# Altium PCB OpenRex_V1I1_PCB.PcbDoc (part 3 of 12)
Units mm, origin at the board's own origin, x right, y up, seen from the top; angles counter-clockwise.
Board outline 70 x 95 mm, 10 copper layers (L1, L2, L3, L4 (PWR), L5 (PWR), L6 (PWR), L7 (PWR), L8, L9, L10), stack 1.632 mm thick; 1080 components, 708 nets, 3831 pads, 2373 vias.
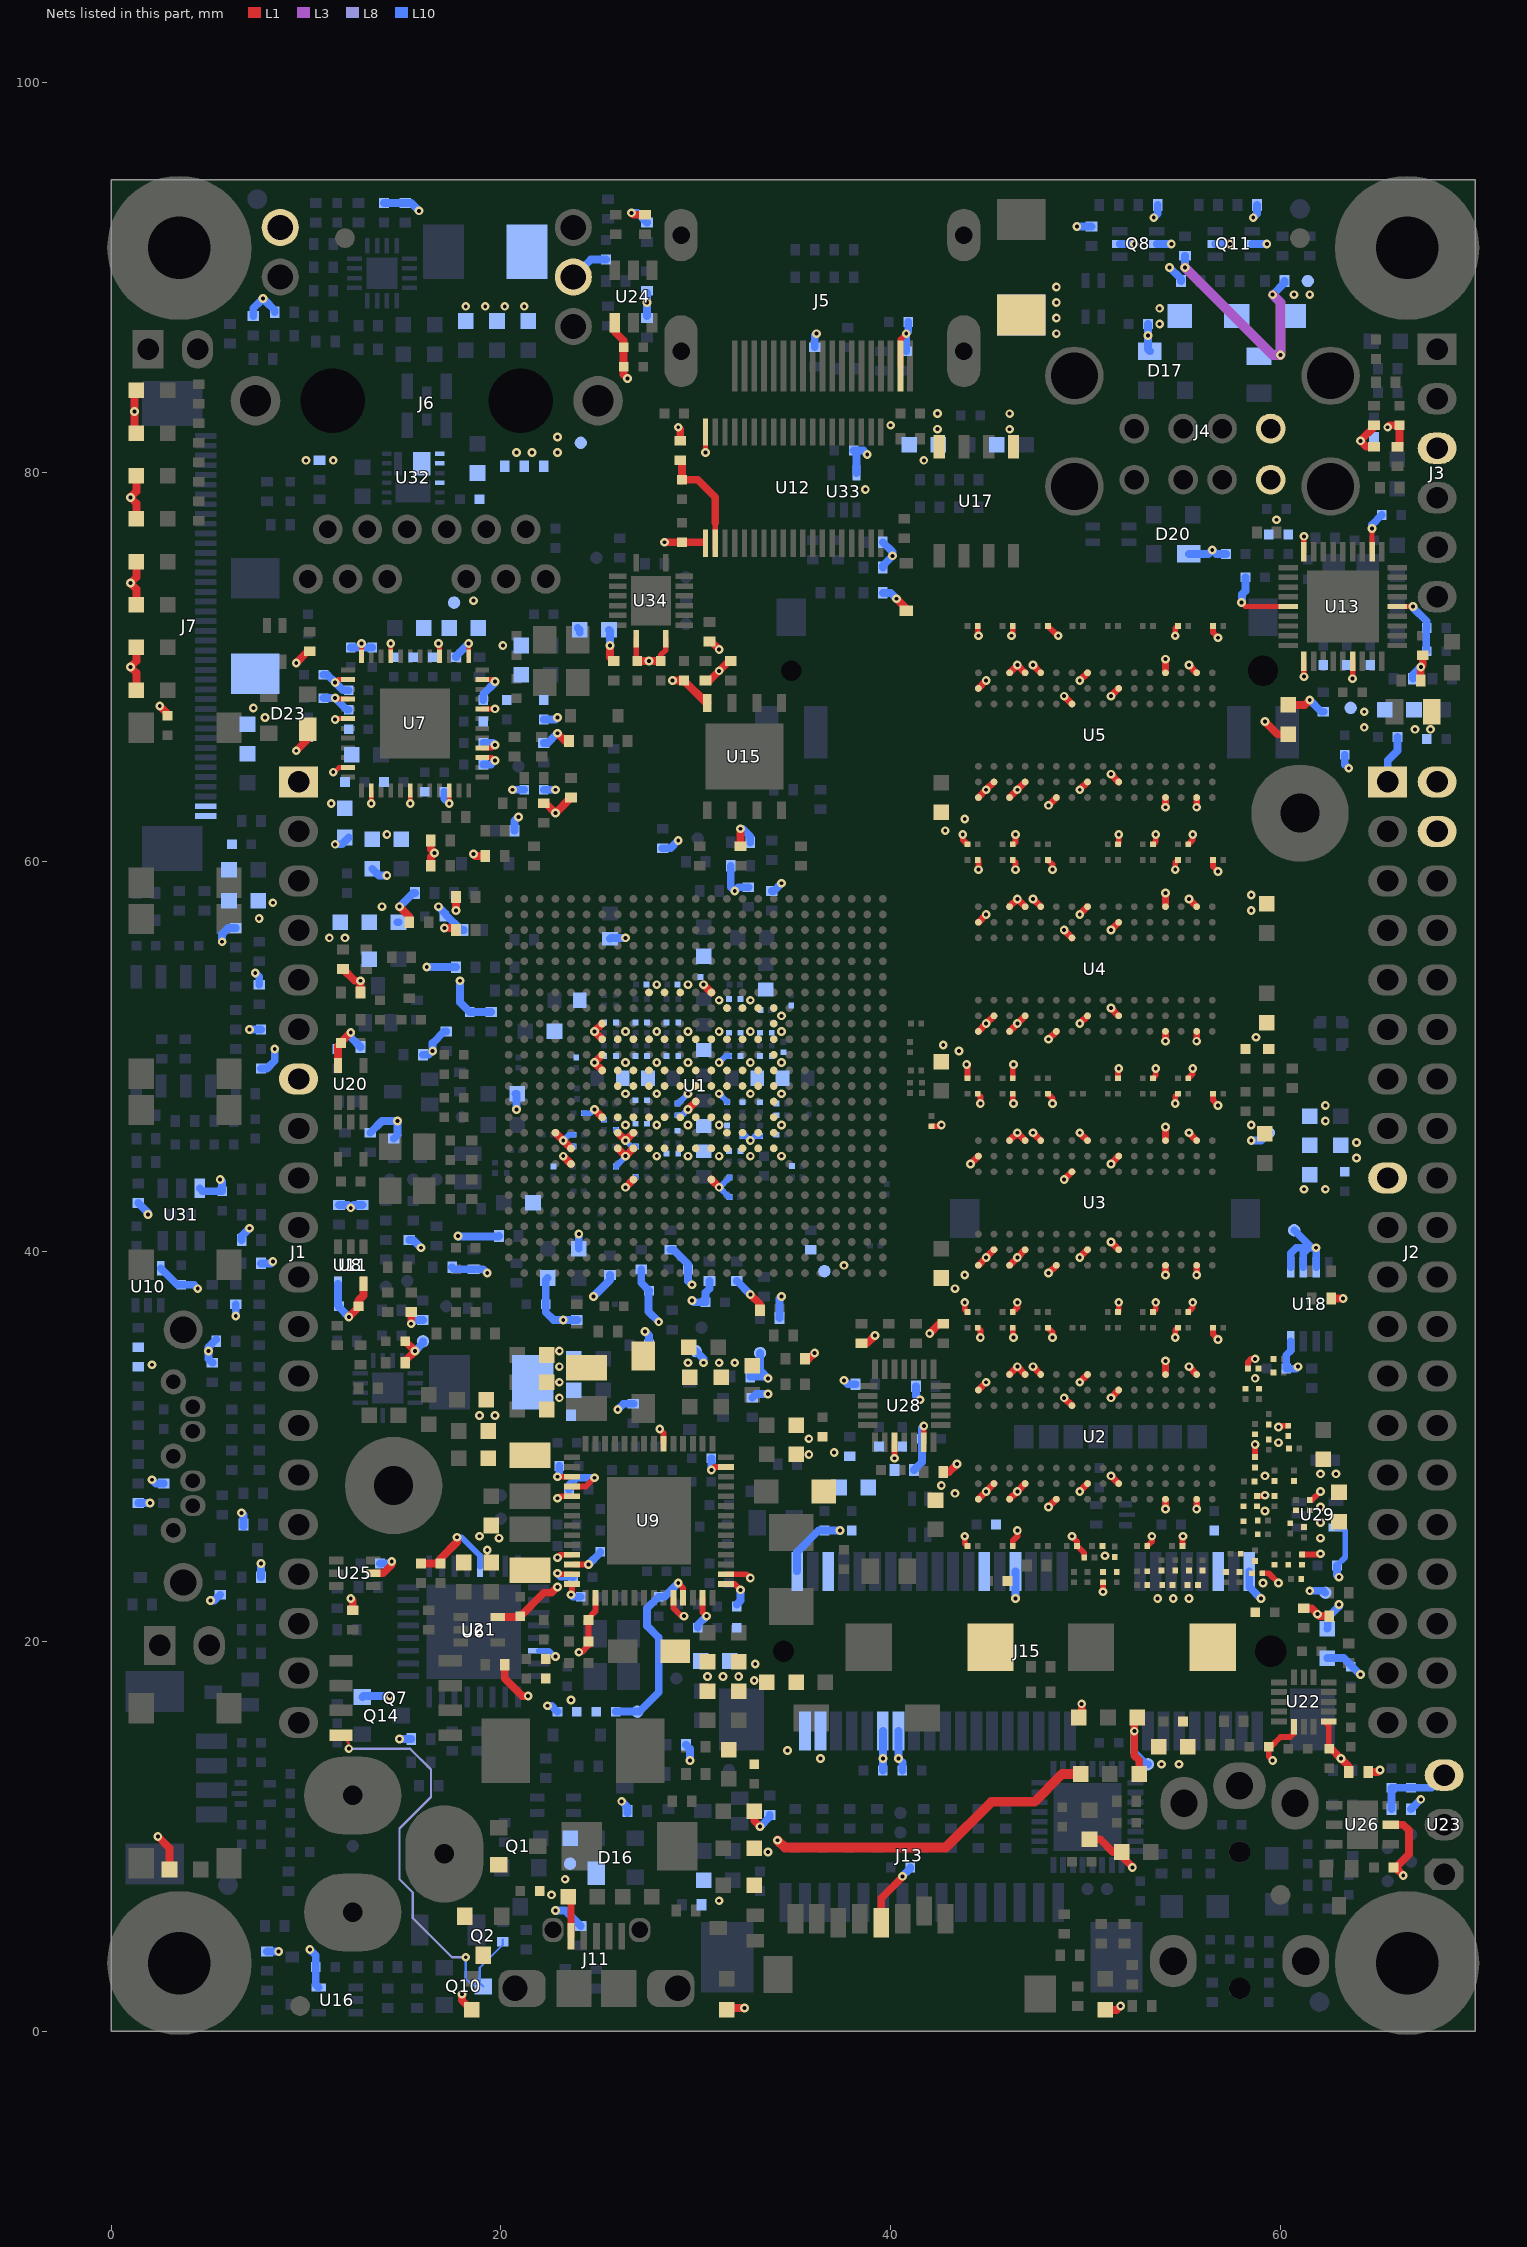
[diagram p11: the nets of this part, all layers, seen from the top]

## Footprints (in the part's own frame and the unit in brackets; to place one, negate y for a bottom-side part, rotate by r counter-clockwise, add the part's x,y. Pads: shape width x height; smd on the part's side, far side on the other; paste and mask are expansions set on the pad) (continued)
SC70_5 [mm]
  rect 0.75x0.4 smd mask+0.025: 1(-0.95,0.65) 2(-0.95,0) 3(-0.95,-0.65) 4(0.95,-0.65) 5(0.95,0.65)
  silkscreen extent -0.76,-1.14 0.76,1.14, body extent -1.21,-1.14 1.21,1.14, height 1.1
SC70_6 [mm]
  rect 0.75x0.4 smd mask+0.025: 1(-0.95,0.65) 2(-0.95,0) 3(-0.95,-0.65) 4(0.95,-0.65) 5(0.95,0) 6(0.95,0.65)
  silkscreen extent -0.76,-1.14 0.76,1.14, body extent -1.21,-1.14 1.22,1.14, height 1.1
SC70_SOT323 [mm]
  rect 0.9x0.7 smd: 1(-0.95,0.65) 2(-0.95,-0.65) 3(0.95,0)
  silkscreen extent -0.7,-1.27 0.7,1.27, body extent -1.27,-1.27 1.27,1.27, height 1.1
SIM_MICRO_HINGED [mm] "Creator MM"
  rect 1x1.2 smd mask+0.06: C1(-4.72,-5.6) C2(-2.18,-5.6) C3(0.36,-5.6) C4(2.9,-5.6) C5(-3.45,-5.6) C6(-0.91,-5.6) C7(1.63,-5.6) C8(4.17,-5.6)
  rect 1.5x2 smd: G1(-7.2,5.6) G2(7.2,5.6)
  silkscreen extent -7.5,-5.9 7.5,10.6, body extent -7.7,-5.8 7.7,10.5, height 1.87
SMC [mm]
  rect 2.5x3.3 smd: 1(-3.45,0) 2(3.45,0)
  silkscreen extent -4.6,-3.2 4.65,3.2, body extent -3.98,-2.95 3.97,2.95, height 2.3
SOD323 [mil]
  rect 22x27 smd mask+3: 1(-48,0) 2(48,0)
  silkscreen extent -75,-28 71,28, body extent -49,-25 49,25, height 39
SOD-123FL [mm] "Wider inside part of pads. Creator MM"
  rect 1.25x1.22 smd: 1(-1.475,0) 2(1.475,0)
  silkscreen extent -2.5,-0.9 2.4,0.9, body extent -1.8,-0.82 1.8,0.83, height 0.95
SOT23-6_DBV6 [mm]
  rect 1x0.55 smd: 1(-1.35,0.95) 2(-1.35,0) 3(-1.35,-0.95) 4(1.35,-0.95) 5(1.35,0) 6(1.35,0.95)
  silkscreen extent -1.6,-1.53 0.9,1.7, body extent -1.5,-1.5 1.5,1.5, height 1.45
SOT143 [mm]
  rect 0.9x1.2 smd: 1(-1,0.8)
  rect 0.9x0.8 smd: 2(-1,-1) 3(1,-1) 4(1,1)
  silkscreen extent -1,-1.7 1,1.7, body extent -1,-1.7 1,1.7, height 1
SOT363 [mm] "Creator MM Used Diodes land pattern as suggested"
  rect 0.8x0.42 smd mask+0.06: 1(-0.95,0.65) 2(-0.95,0) 3(-0.95,-0.65) 4(0.95,-0.65) 5(0.95,0) 6(0.95,0.65)
  silkscreen extent -1.4,-1.2 0.7,1.4, body extent -1.2,-1.1 1.2,1.1, height 1.1
SOT665 [mm] "Creator MM"
  rect 0.65x0.325 smd mask+0.05: 1(-0.75,0.538) 3(-0.75,-0.538)
  rect 0.8x0.25 smd mask+0.05: 2(-0.825,0)
  rect 0.65x0.4 smd mask+0.05: 4(0.75,-0.5) 5(0.75,0.5)
  silkscreen extent -1.2,-0.92 0.8,1.2, body extent -0.8,-0.8 0.8,0.8, height 0.6
SOT-23-3-123 [mm]
  rect 0.9x0.8 smd: 1(-1,0.95) 2(-1,-0.95) 3(1,0)
  silkscreen extent -0.76,-1.65 0.76,1.65, body extent -1.27,-1.65 1.27,1.65, height 1.1
TACT_SMD [mm]
  rect 1.55x1.3 smd mask+0.06: 1(-3.975,2.25) 2(3.975,2.25) 3(-3.975,-2.25) 4(3.975,-2.25)
  silkscreen extent -3.1,-3.1 3.1,3.1, body extent -4.5,-3 4.5,3, height 5
TP_25C [mm]
  round 0.635 smd paste-0.635 mask+0.051: 1(0,0)
TSOP382 [mm] "Creator MM"
  oct 2x1.6 hole 1.1 mask+0.03: 1(0,0)
  oval 2x1.6 hole 1.1 mask+0.03: 2(0,-2.54) 3(0,-5.08)
  silkscreen extent -3.75,-5.2 1.6,0.1, body extent -3.57,-5.33 1.6,0.25, height 10
TSSOP_38 [mm]
  rect 1.4x0.28 smd mask+0.025: 1(-2.85,4.5) 2(-2.85,4) 3(-2.85,3.5) 4(-2.85,3) 5(-2.85,2.5) 6(-2.85,2) 7(-2.85,1.5) 8(-2.85,1) 9(-2.85,0.5) 10(-2.85,0) 11(-2.85,-0.5) 12(-2.85,-1) 13(-2.85,-1.5) 14(-2.85,-2) 15(-2.85,-2.5) 16(-2.85,-3) 17(-2.85,-3.5) 18(-2.85,-4) 19(-2.85,-4.5) 20(2.85,-4.5) 21(2.85,-4) 22(2.85,-3.5) 23(2.85,-3) 24(2.85,-2.5) 25(2.85,-2) 26(2.85,-1.5) 27(2.85,-1) 28(2.85,-0.5) 29(2.85,0) 30(2.85,0.5) 31(2.85,1) 32(2.85,1.5) 33(2.85,2) 34(2.85,2.5) 35(2.85,3) 36(2.85,3.5) 37(2.85,4) 38(2.85,4.5)
  silkscreen extent -3.1,-5 2.3,5.1, body extent -2.3,-5 2.3,5, height 1.2
USB-2A [mm] "Creator MM"
  round 1.524 hole 1: 1(3.5,0.13) 2(1,0.13) 3(-1,0.13) 4(-3.5,0.13) 5(3.5,-2.49) 6(1,-2.49) 7(-1,-2.49) 8(-3.5,-2.49)
  round 3 hole 2.4: 9(-6.57,2.84) 10(6.57,2.84) 11(-6.57,-2.84) 12(6.57,-2.84)
  silkscreen extent -10.75,-4.5 10.75,18.4, body extent -8.1,-4.1 8.14,13.08, height 15.78
USB_MICRO_AB [mm] "Creator MM"
  rect 1.35x0.35 smd mask+0.025: 1(2.675,1.3) 2(2.675,0.65) 3(2.675,0) 4(2.675,-0.65) 5(2.675,-1.3)
  rrect84% 1.25x1.1 hole 0.85 mask+0.04: 6(3,2.225) 7(3,-2.225)
  rrect60% 1.9x2.425 hole 1.3 copper offset 0,-0.363: 8(0,4.175)
  rect 1.9x1.8 smd paste-10: 9(0,1.15) 10(0,-1.15)
  rrect60% 1.9x2.425 hole 1.3 copper offset 0,0.363: 11(0,-4.175)
  silkscreen extent -4.75,-5.4 2.85,5.4, body extent -2.75,-4.32 3.04,4.33, height 2.76
WSON8_6X5MM [mm] "Creator MM"
  rect 0.9x0.45 smd: 1(-2.75,1.905) 2(-2.75,0.635) 3(-2.75,-0.635) 4(-2.75,-1.905) 5(2.75,-1.905) 6(2.75,-0.635) 7(2.75,0.635) 8(2.75,1.905)
  rect 3.4x4 smd: 9(0,0)
  silkscreen extent -3.1,-2.6 3.1,3.1, body extent -3,-2.5 3,2.5, height 0.8
ZIF_RA_BOTTOM_15X1MM [mm] ".Creator MM Added overlay if not moutef properly"
  rect 0.61x2 smd: 1(-7,1.4) 2(-6,1.4) 3(-5,1.4) 4(-4,1.4) 5(-3,1.4) 6(-2,1.4) 7(-1,1.4) 8(0,1.4) 9(1,1.4) 10(2,1.4) 11(3,1.4) 12(4,1.4) 13(5,1.4) 14(6,1.4) 15(7,1.4)
  rect 2.68x3.6 smd: 16(-9.99,-1.4) 17(9.99,-1.4)
  silkscreen extent -11.6,-7 11.6,1.5, body extent -11.46,-5.04 11.46,1.5, height 2.53

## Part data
C1 C2 C3 C4 C5 C6 C8 C9 C10 C11 C12 C21 C22 C23 C24 C25 C26 C30 C34 C35 C36 C37 C38 C39 C40 C41 C42 C43 C44 C45 C46 C47 C48 C49 C50 C51 C52 C53 C54 C55 C56 C57 C58 C59 C60 C61 C62 C64 C68 C73 C75 C76 C77 C79 C81 C82 C90 C91 C92 C93 C94 C95 C97 C98 C99 C100 C102 C103 C104 C105 C107 C108 C109 C110 C112 C113 C114 C115 C116 C117 C119 C120 C121 C122 C123 C124 C125 C126 C130 C131 C132 C133 C134 C136 C138 C140 C142 C143 C144 C145 C146 C149 C150 C152 C154 C155 C157 C158 C159 C160 C161 C162 C163 C164 C165 C166 C167 C168 C169 C170 C171 C174 C203 C204 C205: library part C0603X5R0J224M030BB, "CAP CER 0.22UF 6.3V 20% X5R 0201"
C7 C13 C14 C15 C16 C17 C18 C74 C85 C86 C206 C229 C277 C297 C305 C306 C308 C317 C318 C319 C320 C322 C323: library part C0603X5R1C104K030BC, "CAP CER 0.1UF 16V 10% X5R 0201"
C19 C80 C180 C186 C191 C194 C199 C225 C227 C231 C239 C240 C278 C280 C299 C419: library part C1608X5R0J106M, "CAP CER 10UF 6.3V X5R 20% 0603"
C20 C27 C28 C29 C31 C32 C33 C321 C352 C353 C354 C355 C356 C357 C358 C359 C360 C361 C362 C363 C408 C409 C424 C425 C429 C430 C431: library part GRM188R60G226MEA0L, "CAP CER 22UF 4V 20% X5R 0603"
C63 C65 C66 C67 C87 C89 C181 C187 C190 C192 C195 C207 C213 C214 C215 C216 C217 C218 C219 C221 C226 C228 C230 C232 C235 C236 C243 C250 C252 C255 C256 C259 C260 C261 C265 C266 C267 C268 C269 C270 C272 C273 C274 C275 C276 C279 C281 C282 C283 C284 C285 C292 C294 C296 C298 C300 C301 C302 C303 C307 C309 C310 C314 C315 C316 C324 C325 C329 C340 C341 C342 C345 C346 C349 C350 C368 C370 C371 C374 C380 C382 C383 C384 C385 C386 C388 C389 C392 C393 C395 C398 C399 C401 C402 C403 C405 C412 C413 C414 C416 C417 C418 C420 C422 C423 C435: library part C1005X5R1H104K, "CAP CER .10UF 50V X5R 10% 0402"
C69 C70 C71 C72 C182 C183 C184 C185 C188 C189 C193 C196 C197 C198 C200 C201 C202 C220 C222 C248 C249 C313 C396 C404: library part C1005X7R1H103K, "CAP CER 10000PF 50V 10% X7R 0402"
C78 C208 C209 C244 C245 C246 C247 C251 C262 C263 C264 C333 C336 C344 C347 C348 C351 C369 C372 C373 C387 C391 C397: library part C1005X5R1A475M, "CAP CER 4.7UF 10V 20% X5R 0402"
C83 C84 C223 C224 C242 C415: library part C1005C0G1H180J, "CAP CER 18PF 50V C0G 5% 0402"
C88 C233 C234 C238: library part TPSC107K010R0150, "CAP TANT 100UF 10V 10% 2312"
C96 C101 C106 C111 C118 C127 C128 C129 C135 C172 C173: library part GRM188R60G226MEA0L_small, "CAP CER 22UF 4V 20% X5R 0603"
C137 C141 C147 C148 C151 C156 C364 C365 C381 C406 C407 C426 C427 C428: library part C1608X5R0J226M080AC, "CAP CER 22UF 6.3V 20% X5R 0603"
C139: library part C0603X5R1C103K030BA, "CAP CER .01UF 16V 10% X5R 0201"
C153 C378 C390: library part C1005X5R1E224M, "CAP CER .22UF 25V X5R 20% 0402"
C175 C176 C177 C178 C179 C210 C410 C432: library part C1005C0G1H220J, "CAP CER 22PF 50V C0G 5% 0402"
C211 C212: library part C0603C0G1H180J030BA, "CAP CER 18PF 50V 5% C0G 0201"
C237 C253 C254 C271 C293 C326 C330 C332 C335 C339 C375 C377 C379 C394 C400 C437: library part C1005X5R1C105K, "CAP CER 1.0UF 16V X5R 0402"
C241: library part GRM1555C1H561JA01D, "CAP CER 560PF 50V C0G 0402"
C257 C258: library part T520D337M006ATE045, "CAP TANT 330UF 6.3V 20% 2917"
C286 C287 C295: library part GRM155R71H271KA01D, "CAP CER 270PF 50V 10% X7R 0402"
C288 C289 C311 C312: library part C1005C0G1H101J, "CAP CER 100PF 50V 5% NP0 0402"
C290 C291: library part TLNS227M004R3000, "CAP TANT 220UF 4V 20% 1206"
C304 C367 C376 C421: library part C2012X5R1C106M, "CAP CER 10UF 16V 20% X5R 0805"
C327 C328: library part C0603C0G1H2R2C030BA, "CAP CER 2.2PF 50V C0G 0201"
C331 C334 C337 C338 C436: library part C1005X5R1A225K, "CAP CER 2.2UF 10V 10% X5R 0402"
C343: library part C1005X5R1C474K, "CAP CER .47UF 16V X5R 0402"
C366 C434: library part C1608X5R1A226M080AC, "CAP CER 22UF 10V X5R 0603"
C411 C433: library part C1005X7R1H221K, "CAP CER 220PF 50V X7R 10% 0402"
CR1: library part Card_Mini_PCIe, "Card MIni PCIe"
CR2: library part Card_Micro_SD, "Card Micro SD"
CR3: library part Card_Micro_SIM, "Card Micro SIM"
D1 D2 D3 D5 D6 D7 D33 D34: library part "LS L29K-H1J2-1-Z", "LED SMARTLED RED 630NM 0603 SMD"
D4 D8 D19 D31 D32: "SUPPRESSOR ESD 24VDC 0603 SMD"
D9: "DIODE GEN PURP 1KV 8A SMC"
D10 D27 D28 D29 D35 D36 D39: "DIODE SCHTKY 30MA 30V SOD-323"
D11 D22 D25 D26: library part "LG L29K-G2J1-24-Z", "LED SMARTLED GREEN 570NM 0603"
D12 D14 D21 D24: library part "LO L29K-H2K1-24-Z", "LED SMARTLED ORANGE 606NM 0603"
D13: "DIODE SCHOTTKY 30V 0.2A SOD323"
D15 D37: "TVS ZENER QUAD 5.6V SOT665"
D16 D17 D20 D23: "DIODE SWITCHING 50V SOT-143"
D18 D30 D38: "DIODE SCHOTTKY 40V 1A SOD123L"
FB1 FB2 FB9 FB10 FB14 FB16 FB17 FB31 FB32 FB34 FB35 FB37 FB39 FB40 FB41 FB42: library part BLM18SG221TN1D, "FERRITE CHIP 220 OHM 2500MA 0603"
FB3 FB4 FB6 FB7: "FERRITE CHIP 100 OHM BEAD 0603 3A"
FB5 FB18 FB21 FB22 FB29 FB30 FB43 FB44: "FERRITE CHIP 600 OHM 0402 420mA"
FB8: library part BLM15AX300SN1D, "FERRITE CHIP 30 OHM 1100MA 0402"
FB11 FB12 FB13 FB19 FB20 FB23 FB24 FB26 FB33 FB36 FB38: library part MPZ1608S601A, "FERRITE CHIP BEAD 600 OHM SMD 1A"
FB15 FB25 FB27 FB28: library part BLM15PD121SN1D, "FERRITE CHIP 120 OHM 1300MA 0402"
FID1 FID2 FID3 FID4 FID5 FID6 FID7 FID8: "Fiducial 40mil Diameter, 52mil Mask"
J1: "CONN RCPT 20POS .100\" DUAL GOLD"
J2: "CONN RCPT 40POS .100\" DUAL GOLD"
J3: library part 68001-206HLF, "CONN HEADER 6POS .100 STR 15AU"
J4: library part 5787617-1_v1.1, "CONN RCPT R/A 4OVER4POS GOLD PCB"
J5: library part 47151-0001_v1.1, "CONN RCPT 19POS HDMI RT ANG SMD"
J6: "CONN MAGJACK 1PORT SHLD 1000BT"
J7: "CONN FPC BOTTOM 40POS 0.50MM R/A"
J8: "CONN SATA HDR 7POS PCB VERT"
J9: library part PJ-002AH_v1.1, "CONN PWR JACK 2.1X5.5MM HIGH CUR"
J10: "CONN HEADER 4POS 1.25MM R/A SMD"
J11: library part 0475890001, "CONN RCPT MICRO USB AB R/A SMD"
J12: "CONN FPC BOTTOM 15POS 1.00MM R/A"
J13: "CONN MICRO SD 8 POS SMD"
J14: "CLIFF ELECTRONIC COMPONENTS - FC68125 - CONNECTOR, PHONO, 3.5MM, JACK, 4POLE"
J15: "CONN MINI EXPRESS CARD 52POS SMD"
J16: "CONN MINI EXPRESS CARD LATCH SMD"
J17: "CONN SMART CARD"
JP1 JP2: library part 68001-202HLF, "BERGSTIK II .100\" SR STRAIGHT"
L1 L2: library part IHLP1212AEER1R0M11, "FIXED IND 1UH 3.9A 33 MOHM SMD"
L3 L4 L5 L6 L7: "CHOKE COMM MODE 90 OHM .4A SMD"
L8 L9 L10: library part IFSC1008ABER1R0M01, "FIXED IND 1UH 2.6A 43 MOHM SMD"
L11: library part IHLP1616ABER2R2M11, "FIXED IND 2.2UH 2.75A 83.5 MOHM"
L12 L13: library part IHLP2020BZER1R0M11, "INDUCTOR POWER 1.0UH 7.5A SMD"
MH1 MH2 MH3 MH4: "Mounting Hole 7.4mm Diameter, 3.2mm Drill"
MH5 MH6: "Mounting Hole 5mm Diameter, 2mm Drill"
Q1 Q2: "MOSFET P-CH 20V 3.6A SOT-23"
Q3 Q4 Q5 Q6 Q9 Q12 Q13: "MOSFET N-CH 60V 310MA SOT323"
Q7: "MOSFET P-CH 30V 8.8A 8-SOIC"
Q8 Q11: "MOSFET 2N-CH 60V 0.3A 6TSSOP"
Q10 Q14: "TRANS PNP 40V 0.2A SOT23"
R1 R2 R3 R11 R12 R22 R31 R34 R38 R39 R40 R42 R44 R45 R50 R66 R72 R77 R79 R103 R105 R106 R107 R108 R111: library part MCR006YRTF47R0, "RES SMD 47 OHM 1% 1/20W 0201"
R4 R5 R8 R9 R10 R306 R307 R308 R309: library part RMCF0201FT240R, "RES 240 OHM 1/20W 1% 0201"
R6 R7: library part RC0201FR-0710KL, "RES 10K OHM 1/20W 1% 0201 SMD"
R13 R14 R18 R19 R24 R25 R26 R27 R29 R33 R36 R41 R46 R51 R60 R65 R67 R70 R71 R74 R76 R78 R80 R88 R93 R104 R117 R119 R120 R121 R122 R123 R125 R126 R127 R128 R129 R135 R136 R138 R139 R154 R155 R156 R158 R169 R170 R177 R178 R179 R180 R182 R183 R184 R194 R195 R196 R204 R207 R218 R227 R228 R234 R236 R238 R241 R242 R243 R247 R248 R258 R259 R271 R273 R276 R277 R278 R279 R281 R282 R287 R288 R297 R298 R304 R311 R313 R314 R316 R318 R320 R321 R322 R323 R324 R325 R326 R327 R328 R329 R330 R331 R332 R333 R334 R340 R341 R342 R343 R345 R348 R350 R351 R352 R353 R354 R355 R357 R361 R362 R363 R364 R366 R367 R368 R369 R373 R374 R378 R384 R389 R390 R391 R392 R397 R404 R406 R407 R411 R412 R413: library part RC0402JR-070RL, "RES 0.0 OHM 1/16W 0402 SMD"
R15 R48 R49 R52 R53 R54 R57 R58 R59 R62 R63 R64 R68 R69 R75 R91 R94 R95 R96 R97 R98 R109 R110 R114 R115 R116 R140 R143 R144 R147 R150 R151 R159 R163 R164 R166 R173 R174 R175 R191 R197 R198 R199 R201 R208 R209 R210 R211 R212 R213 R225 R229 R240 R244 R250 R251 R252 R265 R270 R272 R280 R283 R284 R285 R286 R289 R293 R303 R305 R310 R312 R315 R317 R319 R335 R359 R360 R380 R381 R382 R383 R398 R405 R410: library part RC0402FR-0710KL, "RES 10.0K OHM 1/16W 1% 0402 SMD"
R16 R17: library part RC0402FR-0749R9L, "RES 49.9 OHM 1/16W 1% 0402 SMD"
R20: library part CRCW04022M20FKED, "RES 2.20M OHM 1/16W 1% 0402 SMD"
R21 R118 R237 R263 R264 R356 R403: library part RC0402FR-0747KL, "RES 47.0K OHM 1/16W 1% 0402 SMD"
R23: library part ERJ-2RKF1601X, "RES 1.6K OHM 1/10W 1% 0402 SMD"
R28 R87 R89 R132 R133 R134 R137 R142 R148 R157 R171 R172 R187 R188 R205 R257 R290 R291 R302: library part RMCF0402FT4K99, "RES TF 4.99K OHM 1% 1/16W 0402"
R30 R101 R102 R162 R219 R346: library part RC0402FR-071KL, "RES 1.00K OHM 1/16W 1% 0402 SMD"
R32: library part CRCW02011K60FKED, "RES 1.60K OHM 1/20W 1% 0201 SMD"
R35 R43 R83 R85 R86 R90 R92 R124 R130 R131 R152 R153 R161 R181 R206 R275: library part RC0402FR-0722RL, "RES 22.0 OHM 1/16W 1% 0402 SMD"
R37: library part CRCW0402200RFKED, "RES 200 OHM 1/16W 1% 0402 SMD"
R47 R230 R231: library part RC0402FR-0715KL, "RES 15.0K OHM 1/16W 1% 0402 SMD"
R55 R56: library part RMCF0201FT4K99, "RES 4.99K OHM 1/20W 1% 0201"
R61: library part RC0201FR-071KL, "RES 1K OHM 1/20W 1% 0201 SMD"
R73 R203 R214 R215 R216 R217 R220 R221 R223 R224 R239 R261 R262 R266 R338 R344 R347 R365 R385 R393 R394 R395 R396 R401 R408: library part RMCF0402FT100K, "RES 100K OHM 1/16W 1% 0402 SMD"
R81 R82: library part RC0402FR-07220RL, "RES 220 OHM 1/16W 1% 0402 SMD"
R84: library part RC0402FR-0712K1L, "RES SMD 12.1K OHM 1% 1/16W 0402"
R99: library part ERJ-1GEF1910C, "RES 191 OHM 1/20W 1% 0201 SMD"
R100: library part RNCP1206FTD1K00, "RES SMD 1K OHM 1% 1/2W 1206"
R112 R113 R253 R256: library part MCR006YRTF49R9, "RES 49.9 OHM 1/20W 1% 0201 SMD"
R141 R149 R232 R233 R254 R255 R299 R300: library part RMCF0402FT33R0, "RES TF 33 OHM 1% 1/16W 0402"
R145 R165 R176 R189 R192 R193 R200 R202 R387: library part RC0402FR-071K5L, "RES 1.50K OHM 1/16W 1% 0402 SMD"
R146 R185 R186 R226 R245 R274 R379: library part RMCF0402FT240R, "RES TF 240 OHM 1% 0.0625W 0402"
R160: library part ERJ-1GEF6041C, "RES 6.04K OHM 1/20W 1% 0201 SMD"
R167: library part CRCW040210M0FKED, "RES 10.0M OHM 1/16W 1% 0402 SMD"
R168: library part MCR006YZPF1005, "RES 10M OHM 1/20W 1% 0201 SMD"
R190: library part RC0402FR-0727KL, "RES 27.0K OHM 1/16W 1% 0402 SMD"
R222: library part RC0402FR-0712KL, "RES 12.0K OHM 1/16W 1% 0402 SMD"
R235: library part RC0402FR-072K2L, "RES 2.20K OHM 1/16W 1% 0402 SMD"
R246 R249: library part RC0402FR-0760R4L, "RES SMD 60.4 OHM 1% 1/16W 0402"
R260: library part RC0201FR-07100KL, "RES 100K OHM 1/20W 1% 0201 SMD"
R267 R268 R269: library part CRCW0402330RFKED, "RES 330 OHM 1/16W 1% 0402 SMD"
R292: library part CRCW040211K8FKED, "RES 11.8K OHM 1/16W 1% 0402 SMD"
R294 R295: library part RC0805JR-070RL_small, "RES 0.0 OHM 1/8W 0805 SMD"
R296: library part CRCW040210K5FKED, "RES 10.5K OHM 1/16W 1% 0402 SMD"
R301: library part CRCW0402470KFKED, "RES 470K OHM 1/16W 1% 0402 SMD"
R336: library part RC0402FR-0782KL, "RES 82.0K OHM 1/16W 1% 0402 SMD"
R337 R400: library part RC0402FR-07150KL, "RES 150K OHM 1/16W 1% 0402 SMD"
R339: library part CRCW040263K4FKED, "RES SMD 63.4K OHM 1% 1/16W 0402"
R358: library part RC0402FR-071ML, "RES 1.00M OHM 1/16W 1% 0402 SMD"
R370 R371 R372 R375 R376 R377: library part RC0402FR-073K3L, "RES 3.30K OHM 1/16W 1% 0402 SMD"
R386: library part RC0402FR-0724KL, "RES SMD 24K OHM 1% 1/16W 0402"
R388: library part RC0402FR-073KL, "RES 3K OHM 1/16W 1% 0402 SMD"
R399: library part CRCW0402390KFKED, "RES 390K OHM 1/16W 1% 0402 SMD"
R402: library part RC0402FR-0786K6L, "RES SMD 86.6K OHM 1% 1/16W 0402"
SW1 SW2 SW3 SW4: "SWITCH TACTILE SPST-NO 0.05A 12V"
TP1 TP2 TP3 TP4 TP5 TP6 TP7 TP8 TP9 TP10 TP11 TP12 TP13 TP14 TP15 TP16 TP17 TP18 TP19 TP20 TP21 TP22 TP23 TP24 TP25 TP26 TP27 TP28 TP29 TP30 TP31 TP32 TP33 TP34 TP35 TP36 TP37 TP38 TP39 TP40 TP41: "Test Point 25mil"
U1: "IC MCU 32BIT ARM QUAD 624FCBGA"
U2 U3 U4 U5: "IC DDR3 SDRAM 4GBIT 800MHZ FBGA"
U6: library part LPC1345FHN33,551, "IC MCU ARM 32KB FLASH 32HVQFN"
U7: "IC TXRX ETHERNET 48-QFN"
U8 U10 U21: "IC GATE AND 1CH 2-INP SC-70-5"
U9: "IC PWR MGMT I.MX6 56QFN"
U11 U20 U35: "SINGLE POSITIVE AND GATE SC-70"
U12: "IC HDMI TX PORT P/I 38-TSSOP"
U13: "USB HUB CONT IND TEMP 36QFNE3"
U14: "IC AUDIO CODEC STEREO 32-QFN"
U15: "IC FLASH 32MBIT"
U16: "IC BUFF CMOS LVL/SFTR N-I SOT353"
U17: "IC SW DISTRIBUTION 2CHAN 8SOIC"
U18: "IC EEPROM 2KBIT 400KHZ 8MSOP"
U19: library part TJA1040T/CM,118, "IC TRANSCEIVER CAN 8SOIC"
U22: "SENSOR XTRINSIC 6-AXIS QFN"
U23: "IC IR RCVR MOD 38KHZ DOME AXIAL"
U24: "IC DIGITAL TEMP SENSOR SOT23-6"
U25: "IC SWITCH SPDT SC70-6"
U26: "SENSIRION - SHT21 - SENSOR, HUMIDITY & TEMP, 3X3MM, 2%"
U27: "IC VREF SHUNT ADJ SOT23-3"
U28: "GYROSCOPE 3-AXIS 24QFN"
U29: "IC SGL SCHMT-TRIG INVERT SC70-5"
U30 U36: "IC REG BUCK SYNC ADJ 4A 16TQFN"
U31: library part TPS3808G09DBVR, "IC VOLT SUPERVISOR 0.9V SOT23-6"
U32: "IC PWM REG 600mA 1.2V 12-MLF"
U33: "IC BUFFER SCHMIT TRIG SC705"
U34: "IC BUS TRANSCVR 4BIT 16QFN"
Y1 Y4: library part ABM8-24.000MHZ-R60-D-1-W-T, "CRYSTAL 24MHZ 18PF SMD"
Y2: library part ABS06-32.768KHZ-9-1-T, "CRYSTAL 32.768 KHZ 9.0 PF SMD"
Y3: library part ABM8G-25.000MHZ-18-D2Y-T, "CRYSTAL 25MHZ 18PF SMD"
Y5: "CRYSTAL 12MHZ 12PF SMD"

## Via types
v1: diameter 0.45, hole 0.2, L1 to L10, tented both sides, 2369 vias
v2: diameter 1, hole 0.5, L1 to L10, tented top, 4 vias

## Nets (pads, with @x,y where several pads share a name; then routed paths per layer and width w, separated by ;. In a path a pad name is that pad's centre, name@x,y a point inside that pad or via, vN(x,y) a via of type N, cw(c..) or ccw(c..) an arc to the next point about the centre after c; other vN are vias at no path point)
5V_IN_CTRL: Q7.4 Q10.3 R301.2 | length 22.6
  L1 w0.114: Q7.4@11.8,15.195 12.2,14.795 v1(12.2,14.5)
  L8 w0.12: v1(12.2,14.5) 15.344,14.5 16.415,13.429 16.415,12.015 14.8,10.4 14.8,7.796 15.48,7.116 15.48,5.82 17.5,3.8 v1(18.2,3.8)
  L10 w0.114: v1(18.2,3.8) 18.2,2.7 18.5,2.4 Q10.3@19,2.4 ; Q10.3@19.1,2.3 Q10.3@19,2.4 ; R301.2@20.1,4.7 20.1,4.444 18.915,3.259 18.915,2.485 Q10.3@19,2.4
+0V75_DDR_VTT: C13.2 C14.2 C15.2 C16.2 C17.2 C18.2 C20.2 C74.2 C85.2 C86.2 C206.2 C229.1 C277.1 C297.1 C305.1 C306.1 C308.1 C317.1 C318.1 C319.1 C320.1 C321.1 C362.1 C363.1 C425.1 L9.2 R1.2 R2.2 R3.2 R11.2 R12.2 R22.2 R31.2 R34.2 R38.2 R39.2 R40.2 R42.2 R44.2 R45.2 R50.2 R66.2 R72.2 R77.2 R79.2 R103.2 R105.2 R106.2 R107.2 R108.2 R111.2 TP14.1 U9.19 | length 1.6
  L1 w0.3: v1(22.9,27.35) 23,27.45 U9.19@23.65,27.45
  L10 w0.4: v1(61.5,22.6) 62.2,22.6 TP14.1@62.3,22.5
  other v1: 53.7,22.2 55.3,22.2 59.1,23 51,24.4 59.2,26.7 62.05,26.9 59.2,28.5 62.05,28.6 62.85,28.6 59.9,30.2 18.9,31.6 19.7,31.6 58.7,33.5
+1V1_NVCC_PLL_OUT: C150.1 C151.1 U1.E8 | length 0.6
  L1 w0.4: v1(23.2,44.9) U1.E8@23.6,44.5
  L10 w0.3: v1@23.2,44.865 v1(23.2,44.9)
+1V1_VDDSOC_CAP: C78.1 C112.1 C113.1 C114.1 C115.1 C116.1 C117.1 C118.1 C138.1 C246.1 FB1.1 R13.1 R18.1 R27.1 U1.N12 U1.R10 U1.T10 U1.T13 U1.T14 U1.U10 U1.U13 U1.U14 | length 9.7
  L1 w0.4: v1(29.6,47.3) U1.N12@30,47.7
  L10 w0.3: C138.1@29.065,47 29.3,47 v1(29.6,47.3) ; C112.1@32.4,45.935 32.565,45.935 v1(32.8,45.7) 33.035,45.935 C113.1@33.3,45.935
  L10 w0.4: FB1.1@22.4,38.65 22.3,38.55 C78.1@22.3,37.3 22.3,36.9 22.7,36.5 v1(23.2,36.5) R13.1@23.925,36.5 ; v1(24.75,37.7) 25.6,38.55 R18.1@25.6,38.8 ; R27.1@28.7,40.1 28.858,40.1 29.6,39.358 C246.1@29.6,39.1 29.6,38.5 v1(29.8,38.3)
  other v1: 32.8,48.1 32.8,49.7
+1V2_ETH: FB3.1 FB4.1 FB5.1 FB8.2 R352.2 R353.1 TP9.1 | length 2.2
  L10 w0.4: v1(11.5,60.9) 11.85,60.9 FB3.1@12.2,61.25 ; v1(20.6,63.7) FB8.2@21.2,63.7 ; FB5.1@22.2,67.3 22.8,67.3 v1(22.9,67.4)
  other v1: 18.6,73.4 20.8,81 21.6,81
+1V2_ETH_AVDDL: C186.1 C187.1 C188.1 C189.1 FB4.2 U7.4 U7.9 | length 1.3
  L1 w0.25: U7.9@14.35,70.54 v1(14.35,71.2) ; v1(16.8,71.2) 16.85,71.15 U7.4@16.85,70.54
+1V2_ETH_AVDDL_PLL: C191.1 C192.1 C193.1 FB5.2 U7.44 | length 0.7
  L1 w0.25: U7.44@19.04,67.85 v1(19.7,67.85)
+1V2_ETH_DVDDL: C180.1 C181.1 C182.1 C183.1 C184.1 C185.1 C248.1 C249.1 FB3.2 U7.14 U7.18 U7.23 U7.26 U7.30 U7.39 | length 6.5
  L1 w0.25: v1@11.5,64.65 11.7,64.85 U7.23@12.16,64.85 ; v1(11.5,67.3) 11.55,67.35 U7.18@12.16,67.35 ; v1(11.5,69.2) 11.65,69.35 U7.14@12.16,69.35 ; v1(13.35,63) U7.26@13.35,63.66 ; v1(15.35,63) U7.30@15.35,63.66 ; U7.39@19.04,65.35 19.55,65.35 v1(19.7,65.2)
  L10 w0.4: C181.1@10.9,69.6 11.1,69.6 v1(11.5,69.2) 11.9,68.8 C182.1@12.2,68.8 ; C249.1@19.1,65 19.5,65 v1(19.7,65.2)
  other v1: 11.3,63 11.4,64.6
+1V2_PMIC: C333.1 R353.2 TP33.1 U9.18 | length 3
  L1 w0.3: U9.18@23.65,27.95 24.35,27.95 v1(24.8,28.4)
  L10 w0.4: C333.1@23.5,27.8 23.5,28 23.9,28.4 v1(24.8,28.4)
  other v1: 22.9,81 22.9,81.8
+1V2_REG: C240.1 C241.1 R352.1 U32.7 U32.8 U32.10 U32.15
+1V2_VDD_ARM_CAP: C97.1 C98.1 C99.1 C100.1 C101.1 C102.1 C103.1 C104.1 C105.1 C106.1 U1.H11 U1.H13 U1.J11 U1.J13 U1.K11 U1.K13 U1.L11 U1.L13 U1.M11 U1.M13 U1.N11 U1.N13 U1.P11 U1.P13 U1.R11 U1.R13 | length 1.3
  L10 w0.3: C99.1@29.065,47.6 29.1,47.6 v1(29.6,48.1) ; v1(31.2,48.1) 31.6,47.7 C100.1@31.6,47.665
  other v1: 26.4,46.5 28,46.5 29.6,46.5 31.2,46.5 26.4,48.1 28,48.1
+1V5_DDR: C1.1 C2.1 C12.1 C13.1 C14.1 C15.1 C16.1 C17.1 C18.1 C19.1 C20.1 C21.1 C22.1 C23.1 C24.1 C25.1 C26.1 C27.1 C28.1 C29.1 C30.1 C31.1 C32.1 C33.1 C34.1 C35.1 C36.1 C37.1 C38.1 C39.1 C40.1 C41.1 C42.1 C43.1 C44.1 C45.1 C46.1 C47.1 C48.1 C49.1 C50.1 C51.1 C52.1 C53.1 C54.1 C55.1 C56.1 C57.1 C58.1 C59.1 C60.1 C74.1 C85.1 C86.1 C157.1 C158.1 C159.1 C160.1 C161.1 C162.1 C167.1 C168.1 C169.1 C170.1 C171.1 C172.1 C173.1 C203.1 C204.1 C205.1 C206.1 C322.2 C323.2 C340.1 C356.1 C357.1 C358.1 C359.1 C392.1 C437.1 FB10.2 FB20.1 L2.2 R245.2 R302.2 TP32.1 U1.R18 U1.T18 U1.U18 U1.V9 U1.V10 U1.V11 U1.V12 U1.V13 U1.V14 U1.V15 U1.V16 U1.V17 U1.V18 U2.A1 U2.A8 U2.B2 U2.C1 U2.C9 U2.D2 U2.D9 U2.E9 U2.F1 U2.G7 U2.H2 U2.H9 U2.K2 U2.K8 U2.N1 U2.N9 U2.R1 U2.R9 U3.A1 U3.A8 U3.B2 U3.C1 U3.C9 U3.D2 U3.D9 U3.E9 U3.F1 U3.G7 U3.H2 U3.H9 U3.K2 U3.K8 U3.N1 U3.N9 U3.R1 U3.R9 U4.A1 U4.A8 U4.B2 U4.C1 U4.C9 U4.D2 U4.D9 U4.E9 U4.F1 U4.G7 U4.H2 U4.H9 U4.K2 U4.K8 U4.N1 U4.N9 U4.R1 U4.R9 U5.A1 U5.A8 U5.B2 U5.C1 U5.C9 U5.D2 U5.D9 U5.E9 U5.F1 U5.G7 U5.H2 U5.H9 U5.K2 U5.K8 U5.N1 U5.N9 U5.R1 U5.R9 U9.30 U9.38 | length 95.2
  L1 w0.3: v1(24,19.45) 24.15,19.45 24.5,19.8 C437.1@24.5,20 C340.1@24.5,21.1 24.5,21.2 24.85,21.55 U9.30@24.85,22.25 ; U9.38@28.85,22.25 28.85,21.722 29.272,21.3 v1(29.4,21.3) ; C323.2@42.1,46.435 42.535,46.435 v1(42.6,46.5) ; v1(43.7,61.4) 43.7,61.135 C54.1@43.935,60.9 ; v1(43.8,25.4) 43.8,25.035 C1.1@43.935,24.9 ; v1(43.8,37.4) 43.8,37.035 C34.1@43.935,36.9 ; v1(43.9,49.6) 43.935,49.565 C44.1@43.935,48.9 ; C23.1@44.465,36.1 44.6,35.965 v1(44.6,35.6) ; C39.1@44.465,48.1 44.6,47.965 v1(44.6,47.6) ; C49.1@44.465,60.1 44.5,60.065 v1(44.5,59.6) ; C59.1@44.465,72.1 44.465,71.635 v1(44.5,71.6) ; v1(46.2,71.6) 46.265,71.665 C60.1@46.265,72.1 ; C2.1@46.265,24.9 46.265,25.165 46.5,25.4 v1(46.5,25.7) ; C24.1@46.265,36.1 46.265,35.635 v1(46.3,35.6) ; C40.1@46.265,48.1 46.265,47.635 v1(46.3,47.6) ; C45.1@46.265,48.9 46.265,49.565 v1(46.3,49.6) ; C50.1@46.265,60.1 46.4,59.965 v1(46.4,59.6) ; C55.1@46.295,60.9 46.4,61.005 v1(46.4,61.4) ; C35.1@46.4,37.035 C35.1@46.265,36.9 46.5,37.135 v1(46.5,37.4) ; C25.1@48.065,36.1 48.3,35.865 v1(48.3,35.6) ; C41.1@48.065,48.1 48.3,47.865 v1(48.3,47.6) ; C51.1@48.065,60.1 48.3,59.865 v1(48.3,59.6) ; C203.1@48.065,72.1 v1@48.565,71.6 ; v1(49.3,25.4) 49.368,25.333 49.435,25.265 49.565,25.135 49.565,24.907 49.935,24.537 C322.2@49.935,24.3 ; v1(50.9,22.55) C206.1@50.9,23.035 ; C36.1@51.665,36.9 51.7,36.935 v1(51.7,37.4) ; C46.1@51.665,48.9 51.665,49.365 v1(51.7,49.4) ; C56.1@51.665,60.9 51.7,60.935 v1(51.7,61.4) ; C21.1@53.165,24.9 53.4,25.135 v1(53.4,25.4) ; C37.1@53.465,36.9 53.6,37.035 v1(53.6,37.4) ; C47.1@53.465,48.9 53.6,49.035 v1(53.6,49.4) ; C57.1@53.465,60.9 53.6,61.035 v1(53.6,61.4) ; v1(54.6,35.6) 54.6,35.965 C26.1@54.735,36.1 ; v1(54.6,47.6) 54.6,47.965 C42.1@54.735,48.1 ; v1(54.6,59.6) 54.6,59.965 C52.1@54.735,60.1 ; v1(54.6,71.6) 54.6,71.965 C204.1@54.735,72.1 ; C22.1@54.965,25 54.965,25.365 v1(55,25.4) ; C48.1@55.265,48.9 55.5,49.135 v1(55.5,49.4) ; C58.1@55.265,60.9 55.5,61.135 v1(55.5,61.4) ; C38.1@55.4,37.035 C38.1@55.265,36.9 55.5,37.135 v1(55.5,37.4) ; C30.1@56.535,36.1 56.535,35.765 v1(56.8,35.5) ; C43.1@56.535,48.1 56.535,47.765 v1(56.8,47.5) ; C53.1@56.535,60.1 56.535,59.765 v1(56.8,59.5) ; C205.1@56.535,72.1 56.535,71.765 v1(56.8,71.5) ; C13.1@58.335,34 58.335,34.335 58.5,34.5 v1(58.7,34.5) ; C15.1@58.7,29.465 v1(58.7,30.1) ; C17.1@58.8,27.465 v1@59.165,27.465 ; C74.1@59.065,23.5 59.4,23.5 v1(59.9,23) ; v1(59.9,31) 59.965,31.065 C14.1@60.4,31.065 ; C18.1@61.1,24.465 62.015,24.465 v1(62.05,24.5) ; C16.1@61.5,27.265 61.615,27.265 v1(62.05,27.7)
  L1 w0.35: v1(44.1,44.5) U3.A8@44.5,44.9 ; U2.A1@44.5,27.3 v1(44.9,27.7) U2.B2@45.3,28.1 ; U2.A8@44.5,32.9 v1(44.9,33.3) ; U3.A1@44.5,39.3 v1(44.9,39.7) U3.B2@45.3,40.1 ; U4.A1@44.5,51.3 v1(44.9,51.7) U4.B2@45.3,52.1 ; U4.A8@44.5,56.9 v1(44.9,57.3) ; U5.A1@44.5,63.3 v1(44.9,63.7) U5.B2@45.3,64.1 ; U5.A8@44.5,68.9 v1(44.9,69.3) ; U2.C1@46.1,27.3 v1(46.5,27.7) U2.D2@46.9,28.1 ; U2.C9@46.1,33.7 v1(46.5,34.1) U2.D9@46.9,33.7 ; U3.C1@46.1,39.3 v1(46.5,39.7) U3.D2@46.9,40.1 ; U3.C9@46.1,45.7 v1(46.5,46.1) U3.D9@46.9,45.7 ; U4.C1@46.1,51.3 v1(46.5,51.7) U4.D2@46.9,52.1 ; U4.C9@46.1,57.7 v1(46.5,58.1) U4.D9@46.9,57.7 ; U5.C1@46.1,63.3 v1(46.5,63.7) U5.D2@46.9,64.1 ; U5.C9@46.1,69.7 v1(46.5,70.1) U5.D9@46.9,69.7 ; v1(47.3,34.1) U2.E9@47.7,33.7 ; v1(47.3,46.1) U3.E9@47.7,45.7 ; v1(47.3,58.1) U4.E9@47.7,57.7 ; v1(47.3,70.1) U5.E9@47.7,69.7 ; v1(48.1,26.9) U2.F1@48.5,27.3 ; v1(48.1,38.9) U3.F1@48.5,39.3 ; v1(48.1,50.9) U4.F1@48.5,51.3 ; v1(48.1,62.9) U5.F1@48.5,63.3 ; v1(48.9,32.5) U2.G7@49.3,32.1 ; v1(48.9,43.7) U3.G7@49.3,44.1 ; v1(48.9,56.5) U4.G7@49.3,56.1 ; v1(48.9,68.5) U5.G7@49.3,68.1 ; v1(49.7,27.7) U2.H2@50.1,28.1 ; v1(49.7,33.3) U2.H9@50.1,33.7 ; v1(49.7,39.7) U3.H2@50.1,40.1 ; v1(49.7,46.1) U3.H9@50.1,45.7 ; v1(49.7,51.7) U4.H2@50.1,52.1 ; v1(49.7,57.3) U4.H9@50.1,57.7 ; v1(49.7,63.7) U5.H2@50.1,64.1 ; v1(49.7,69.3) U5.H9@50.1,69.7 ; v1(51.3,28.5) U2.K2@51.7,28.1 ; v1(51.3,32.5) U2.K8@51.7,32.9 ; v1(51.3,40.5) U3.K2@51.7,40.1 ; v1(51.3,44.5) U3.K8@51.7,44.9 ; v1(51.3,52.5) U4.K2@51.7,52.1 ; v1(51.3,56.5) U4.K8@51.7,56.9 ; v1(51.3,64.5) U5.K2@51.7,64.1 ; v1(51.3,68.5) U5.K8@51.7,68.9 ; v1(54.1,26.8) U2.N1@54.1,27.3 ; U2.N9@54.1,33.7 v1(54.1,34.4) ; v1(54.1,38.8) U3.N1@54.1,39.3 ; U3.N9@54.1,45.7 v1(54.1,46.4) ; v1(54.1,50.8) U4.N1@54.1,51.3 ; U4.N9@54.1,57.7 v1(54.1,58.4) ; v1(54.1,62.8) U5.N1@54.1,63.3 ; U5.N9@54.1,69.7 v1(54.1,70.4) ; v1(55.3,34.1) U2.R9@55.7,33.7 ; v1(55.3,46.1) U3.R9@55.7,45.7 ; v1(55.3,58.1) U4.R9@55.7,57.7 ; v1(55.3,70.1) U5.R9@55.7,69.7 ; v1(55.7,26.8) U2.R1@55.7,27.3 ; v1(55.7,38.8) U3.R1@55.7,39.3 ; v1(55.7,50.8) U4.R1@55.7,51.3 ; v1(55.7,62.8) U5.R1@55.7,63.3
  L1 w0.5: v1(34.2,9.8) 34.575,9.425 42.825,9.425 45.175,11.775 47.375,11.775 48.8,13.2 FB20.1@49.75,13.2
  L10 w0.4: R302.2@1.4,42.5 1.9,42 v1(1.9,41.9) ; v1(58.5,45.7) 59,45.7 TP32.1@59.4,46.1
  other v1: 30.6,18.2 31.4,18.2 32.2,18.2 54.5,22.2 62.05,25.3 62.05,26.1 59.2,27.5 43.3,27.6 42.6,28 43.3,38.1 43.8,38.8 34.4,44.9 34.4,46.5 58.5,46.5 34.4,48.1 34.4,49.7 43.5,50.3 42.7,50.6 58.75,51 34.4,51.3 34.4,52.1 31.2,52.9 32.8,52.9 58.5,57.5 58.5,58.3 42.8,61.6 43.8,62.2 48.6,71.6
+1V5_MPCIE: C259.1 C260.1 C261.1 C262.1 FB10.1 J15.6 J15.28 J15.48
+1V8_AUDIO: C334.1 FB11.2 FB26.2 TP34.1 U9.26 | length 6.8
  L1 w0.3: U9.26@23.75,23.95 v1(24.5,23.95)
  L1 w0.4: FB26.2@52.65,16.1 52.5,15.95 v1(52.5,15.4) 52.5,14.15 52.75,13.9 FB11.2@52.75,13.2
  L10 w0.4: v1(24.5,23.95) 25.1,24.55 C334.1@25.1,24.6 ; v1(52.5,15.4) 52.5,14.3 53.1,13.7 TP34.1@53.2,13.7
+1V375_CORE: C90.1 C91.1 C92.1 C93.1 C94.1 C95.1 C96.1 C107.1 C108.1 C109.1 C110.1 C111.1 C352.1 C353.1 C354.1 C355.1 FB8.1 L1.2 R340.2 TP8.1 U1.H14 U1.J14 U1.K9 U1.K14 U1.L9 U1.L14 U1.M9 U1.M14 U1.N9 U1.N14 U1.P9 U1.P14 U1.R9 U1.R14 U1.T9 U1.U9 U9.6 | length 3.8
  L1 w0.3: v1(28.15,30.9) 28.35,30.7 U9.6@28.35,30.15
  L10 w0.3: v1(31.2,49.7) 31.535,50.035 C95.1@31.7,50.035
  L10 w0.4: FB8.1@22.2,63.7 v1(22.8,63.7) ; v1(26,31.9) 26.3,32.2 R340.2@26.8,32.2 ; TP8.1@30,34.9 30.4,34.5 v1(30.4,34.3)
  other v1: 29.6,34.3 31.2,34.3 32,34.3 28,44.9 29.6,44.9 31.2,44.9 32.8,44.9 26.4,49.7 28,49.7 29.6,49.7
+1V375_SOC: C119.1 C120.1 C121.1 C122.1 C123.1 C124.1 C125.1 C126.1 C127.1 C128.1 C129.1 C360.1 C361.1 C408.1 C409.1 C410.2 C424.1 L8.1 L12.2 R336.2 R384.1 TP11.1 U1.H16 U1.J16 U1.K16 U1.L16 U1.M16 U1.N16 U1.P16 U1.R16 U1.T16 U1.U16 | length 3
  L1 w0.4: R336.2@15.1,34.3 15.1,34.4 v1(15.6,34.9) C410.2@15.1,35.4
  L10 w0.4: v1(15.6,34.9) 16,35.3 TP11.1@16,35.4 ; C129.1@25.6,56.05 25.65,56.1 v1(26.4,56.1)
  other v1: 23,32.5 23,33.3 23,34.1 23,34.9 26.4,51.3 28,51.3 29.6,51.3 31.2,51.3 32.8,51.3
+2V5: C153.1 C209.1 C244.1 C247.1 C336.1 FB6.1 R14.1 R19.1 R29.1 R36.1 R74.2 R78.2 R80.2 TP35.1 U9.28 | length 14.5
  L1 w0.3: v1(23.6,22.4) 23.65,22.45 U9.28@23.65,22.95
  L10 w0.4: FB6.1@13.4,59.65 13.75,59.3 v1(14.15,59.3) ; v1(16.8,57.7) 17.175,57.325 17.175,57.283 17.958,56.5 R80.2@18.1,56.5 ; v1(17.8,40.8) 17.825,40.775 19.875,40.775 R14.1@19.9,40.8 ; v1(17.9,53.9) 17.9,52.8 C209.1@18.4,52.3 R19.1@19.5,52.3 ; v1(23.6,22.4) 23.7,22.3 C336.1@24.1,22.3 ; R78.2@27.2,39.1 27.2,38.4 C244.1@27.6,38 27.575,37.975 27.575,36.925 v1(28.1,36.4) ; v1(29.8,37.5) 29.9,37.4 C247.1@30.5,37.4 30.5,37.9 30.7,38.1 R29.1@30.7,38.5 ; R74.2@33.9,58.5 34,58.5 v1(34.4,58.9)
  other v1: 37.6,39.3
+2V5_ETH_DVDDH: C194.1 C195.1 C196.1 C197.1 C198.1 FB6.2 R75.2 R87.2 R89.2 R91.2 R94.2 R95.2 R96.2 R97.2 R98.2 R162.2 U7.16 U7.34 U7.40 | length 13
  L1 w0.25: v1(11.5,68.4) 11.55,68.35 U7.16@12.16,68.35 ; v1(17.35,63) U7.34@17.35,63.66 ; U7.40@19.04,65.85 19.55,65.85 v1(19.7,66)
  L1 w0.4: v1(9.5,70.2) 10.1,70.8 R94.2@10.2,70.8 ; R96.2@16.4,59.8 16.4,60.25 v1(16.6,60.45) 16.4,60.65 R98.2@16.4,61.1 ; v1(17.1,56.6) 17.6,56.6 R91.2@17.7,56.5 ; v1(17.7,57.5) R97.2@17.7,58.2 ; v1(18.6,60.4) 18.7,60.3 R95.2@19.2,60.3 ; R87.2@22.2,63 22.3,63 v1(22.8,62.5) R162.2@23.6,63.3 ; v1(22.9,66.6) 23.3,66.2 R75.2@23.5,66.2
  L10 w0.4: C195.1@10.9,68.4 v1(11.5,68.4) 12.1,67.8 C198.1@12.2,67.8 ; C197.1@17.1,63.6 17.1,63.25 v1(17.35,63) ; C196.1@19.1,66.1 19.6,66.1 v1(19.7,66) ; R89.2@22.2,66.1 22.4,66.1 v1(22.9,66.6)
  other v1: 14.15,61.4
+2V5_VDDHIGH_VPH: C139.1 C140.1 C141.1 U1.H10 U1.J10 | length 3.3
  L1 w0.4: U1.H10@26,46.1 v1(26.4,45.7) U1.J10@26.8,46.1
  L10 w0.3: C139.1@25.9,46.235 25.9,46.2 v1(26.4,45.7) 26.7,45.4 C140.1@26.935,45.4
  L10 w0.4: C141.1@24,40.15 v1(24,40.9)
+3V0_ALWAYS: C87.1 C136.1 C137.1 C142.1 C338.1 C412.1 R48.2 R55.2 R59.2 R73.2 R171.2 R172.2 R173.2 R225.2 R229.2 R264.2 R266.2 R272.2 R405.2 TP37.1 U1.G11 U1.H9 U1.J9 U9.41 U10.5 U31.6 | length 21
  L1 w0.3: U9.41@30.35,22.25 30.35,21.5 v1(30.55,21.3)
  L1 w0.4: v1(24.8,47.3) U1.G11@25.2,46.9 ; U1.H9@26,45.3 v1(26.4,44.9) U1.J9@26.8,45.3
  L10 w0.3: R55.2@24.265,47.1 24.6,47.1 v1(24.8,47.3) 24.8,47.265 C142.1@25.3,46.765 ; C136.1@25.9,44.365 26.4,44.865 v1(26.4,44.9)
  L10 w0.4: U10.5@2.55,39.15 3.4,38.3 C87.1@3.6,38.3 4.25,38.3 v1(4.45,38.1) ; U31.6@4.55,43.25 4.7,43.1 C412.1@5.7,43.1 5.7,43.6 v1(5.6,43.7) ; v1(6.4,36.7) R229.2@6.4,37.3 ; v1(6.7,26.6) 6.8,26.5 R73.2@6.8,26 R73.2@6.8,25.9 ; R405.2@7.7,39.4 8.2,39.4 v1(8.3,39.5) ; R48.2@13.3,46.1 13.9,46.7 v1(14.7,46.7) 14.7,46 R172.2@14.5,45.8 ; R225.2@15.3,40.6 15.5,40.6 v1(15.9,40.2) ; R173.2@16,50.1 16.3,50.1 v1(16.5,50.3) 16.5,50.7 17.1,51.3 R171.2@17.2,51.3 ; v1(20.8,47.3) 20.8,48.05 20.75,48.1 C137.1@20.8,48.1 ; v1(27.4,35.9) 27.6,35.7 R266.2@27.6,35.2 ; C338.1@30.1,20.7 30.1,20.85 v1(30.55,21.3) ; R264.2@32.8,33.6 v1@33.6,33.6 ; TP37.1@33.3,34.8 33.3,33.9 v1@33.6,33.6 ; v1(33.7,33.5) v1@33.6,33.6
  other v1: 2.1,34.2
+3V0_VSNVS: C343.1 R262.2 R347.2 R385.2 U9.43 | length 3.8
  L1 w0.3: U9.43@31.55,22.95 32,22.95 v1(32.3,22.65)
  L10 w0.4: R347.2@1.4,27.1 v1(2,27.1) ; v1(5.1,22.1) 5.3,22.1 R262.2@5.6,22.4 ; R385.2@29.5,14.7 29.7,14.5 v1(29.7,13.9) ; C343.1@32.1,21.9 32.3,22.1 v1(32.3,22.65)
+3V3: C89.1 C144.1 C146.1 C147.1 C148.1 C154.1 C163.1 C164.1 C165.1 C166.1 C174.1 C273.1 C280.1 C296.1 C307.1 C310.1 C324.2 C326.2 C329.1 C330.1 C332.1 C364.1 C365.1 C380.1 C384.1 C386.1 C395.1 C396.1 C405.1 C414.1 C417.1 C418.1 C426.1 D1.2 D2.2 D3.2 D5.2 D6.2 D7.2 D11.2 D13.2 D14.2 D21.2 D22.2 D25.2 D26.2 D30.2 D33.2 D34.2 FB7.1 FB9.1 FB12.1 FB13.2 FB14.1 FB16.1 FB19.1 FB30.1 FB33.1 FB36.1 FB41.2 FB42.2 FB43.1 J6.14 J6.16 J13.4 L10.2 Q8.2 Q8.5 Q11.2 Q11.5 R15.2 R21.2 R28.2 R46.2 R49.2 R57.2 R62.2 R63.2 R64.2 R68.2 R69.2 R76.2 R109.1 R114.2 R116.2 R118.2 R132.2 R133.2 R134.2 R137.2 R140.2 R142.2 R143.2 R147.2 R148.2 R150.2 R151.2 R159.2 R197.2 R198.2 R201.2 R208.2 R209.2 R212.2 R213.2 R226.2 R240.2 R244.2 R251.2 R252.2 R257.2 R258.1 R260.2 R263.2 R280.2 R289.2 R290.2 R291.2 R319.2 R355.1 R356.2 R359.2 R360.2 R370.2 R371.2 R375.2 R376.2 R381.2 R410.2 TP15.1 U1.G14 U1.G15 U1.G16 U1.G17 U1.J7 U1.K19 U1.L19 U1.M19 U1.P7 U1.P19 U8.5 U9.17 U9.25 U9.27 U9.55 U11.5 U15.8 U18.1 U18.2 U18.3 U18.8 U20.5 U24.4 U25.5 U26.5 U29.5 U33.5 U34.1 U34.16 | length 126
  L1 w0.28: U34.16@26.95,71.45 26.95,70.35 C418.1@27,70.3 ; C417.1@28.2,70.3 28.2,70.6 28.45,70.85 U34.1@28.45,71.45
  L1 w0.3: v1@22.9,23.55 23,23.45 U9.27@23.65,23.45 ; v1(22.9,24.3) 23.05,24.45 U9.25@23.65,24.45 ; v1(22.9,28.45) U9.17@23.65,28.45 ; v1(30.8,28.8) 30.95,28.95 U9.55@31.55,28.95
  L1 w0.4: D34.2@1.3,68.8 1.3,69.7 v1(1,70) 1.3,70.3 D7.2@1.3,71 ; D6.2@1.3,73.2 1.3,74 v1(1,74.3) 1.3,74.6 D5.2@1.3,75.4 ; D33.2@1.3,77.6 1.3,78.4 v1(1,78.7) 1.3,79 D3.2@1.3,79.8 ; D2.2@1.3,82 1.2,82.1 v1(1.2,83.1) 1.2,84.1 D1.2@1.3,84.2 ; v1(2.4,10) 3,9.4 D22.2@3,8.3 ; v1(2.5,68) 2.9,67.6 C307.1@2.9,67.5 ; D22.2@3.1,8.2 D22.2@3.1,8.3 ; U20.5@11.65,49.55 11.65,50.55 C310.1@11.8,50.7 11.8,50.75 v1(12.3,51.25) ; R252.2@11.9,54.5 12.5,53.9 v1(12.8,53.9) R251.2@12.8,53.5 ; v1(12.2,36.65) 12.7,37.15 C386.1@12.7,37.2 12.7,37.5 12.95,37.75 U11.5@12.95,38.35 ; v1(12.3,22.2) 12.4,22.1 R289.2@12.4,21.6 ; U25.5@13.45,23.5 13.966,23.5 14.4,23.934 v1(14.4,24.1) ; v1(14.8,57.7) 15.3,57.2 R212.2@15.3,56.9 ; v1(15.4,36.3) R49.2@15.4,36.9 ; U1.G14@25.2,49.3 v1(24.8,49.7) U1.G15@25.2,50.1 ; U1.G16@25.2,50.9 v1(24.8,51.3) U1.G17@25.2,51.7 ; v1(25.6,71.1) 25.6,70.5 R319.2@25.8,70.3 ; U24.4@25.85,87.65 25.85,87.192 26.3,86.742 C396.1@26.3,86.4 C326.2@26.3,85.4 26.3,85 v1(26.5,84.8) ; v1(26.4,43.3) U1.J7@26.8,43.7 ; v1(26.7,93.3) 26.8,93.2 R257.2@27.4,93.2 ; C418.1@27,70.3 v1(27.6,70.3) C417.1@28.2,70.3 ; v1(28.8,69.3) C384.1@29.4,69.3 30.55,68.15 U15.8@30.595,68.15 ; v1(29.1,82.3) 29.2,82.2 R46.2@29.2,81.6 ; v1(30.4,53.7) U1.P19@30.8,53.3 ; R360.2@30.5,69.3 30.7,69.3 v1(31.2,69.8) 31.7,70.3 R109.1@31.8,70.3 ; R359.2@30.7,71.3 30.8,71.3 v1(31.2,70.9) ; U1.P7@30.8,43.7 v1(31.2,43.3) ; D21.2@31.6,1.1 31.7,1.2 v1(32.5,1.2) ; R244.2@32.3,60.8 v1(32.3,61.7) ; v1(32.8,37.8) 33.3,37.3 R151.2@33.3,37 ; D11.2@33,11.3 33,10.8 v1(33.3,10.5) ; R197.2@35.6,34.5 35.8,34.5 v1(36.1,34.8) ; R410.2@38.5,35.3 38.8,35.3 v1(39.2,35.7) ; J13.4@39.515,5.575 39.515,6.823 40.6,7.908 v1(40.6,7.95) ; v1(40.3,73.5) 40.8,73 D13.2@40.8,72.881 ; FB13.2@49.65,16.1 FB13.2@49.65,16.25 ; FB13.2@49.8,16.25 v1(49.8,16.8) ; FB12.1@50.2,9.85 50.75,9.85 51.4,9.2 C280.1@51.65,9.2 ; D14.2@51,1.1 51.6,1.1 v1(51.8,1.3) ; C280.1@51.85,9.2 C280.1@51.65,9.2 ; v1(52.4,8.4) 52.4,8.45 C280.1@51.65,9.2 ; v1(59.2,67.2) 59.85,66.55 FB19.1@60.4,66.55 ; R114.2@62.6,37.6 v1(63.215,37.6) ; U26.5@65.65,10.6 66.3,10.6 66.6,10.3 66.6,9.1 C329.1@66,8.5 ; C329.1@65.8,8.4 65.9,8.4 v1(66.3,8)
  L10 w0.3: v1(26.4,43.3) 26.9,43.8 C174.1@26.9,43.835 ; R260.2@31.735,42.8 31.7,42.8 v1(31.2,43.3) 31.235,43.3 C163.1@31.735,43.8 ; U29.5@62.85,25.85 63.15,25.85 63.325,25.675 63.325,24.325 C405.1@62.9,23.9
  L10 w0.38: U18.8@60.525,35.4 60.525,34.925 60.3,34.7 C324.2@60.3,34 60.8,34 v1(60.9,34.1) ; U18.1@60.525,39.2 60.525,39.925 60.8,40.2 61.45,40.2 ; TP15.1@60.7,41.1 v1@61.6,40.2 ; U18.2@61.175,39.2 61.175,39.925 61.45,40.2 ; U18.3@61.825,39.2 v1(61.825,40.2) v1@61.6,40.2 ; 61.45,40.2 v1@61.6,40.2
  L10 w0.4: v1(2.1,28.3) 2.3,28.1 R140.2@2.7,28.1 ; R148.2@5.2,34.3 5,34.5 v1(5,34.9) 5,35.1 R209.2@5.4,35.5 ; v1(5.7,55.9) 5.7,56.3 6,56.6 R290.2@6.4,56.6 ; R208.2@6.7,40.6 6.7,40.8 v1(7.1,41.2) ; v1(7.1,51.4) FB43.1@7.7,51.4 ; R142.2@7.3,88 7.3,88.4 7.7,88.8 7.9,88.8 R137.2@8.4,88.3 ; v1(7.4,54.3) 7.6,54.1 R291.2@7.6,53.7 ; v1(7.8,88.9) R137.2@8.4,88.3 ; R137.2@8.4,88.2 R137.2@8.4,88.3 ; U8.5@11.65,38.35 11.65,37.25 C89.1@11.7,37.2 11.7,37.15 v1(12.2,36.65) ; R68.2@11.7,42.4 12.15,42.4 v1(12.3,42.25) 12.45,42.4 R69.2@12.9,42.4 ; v1@12.3,51.2 12.3,51 R280.2@12.8,50.5 ; C395.1@13.8,24 14.3,24 v1(14.4,24.1) ; FB42.2@14.7,56.9 FB42.2@14.75,56.9 ; v1(14.8,57.7) 15.5,58.4 R147.2@15.6,58.4 ; v1(15.4,36.3) 15.6,36.5 R62.2@16,36.5 ; v1(16.2,54.6) R143.2@17.7,54.6 ; R64.2@17.5,39.2 17.6,39.1 R63.2@18.6,39.1 19.1,39.1 v1(19.3,38.9) ; R381.2@20.7,61.6 20.7,62.1 v1(20.9,62.3) ; v1(22.4,16.7) 22.6,16.7 FB30.1@22.9,16.4 ; v1(22.8,6.2) 23.3,6.2 R198.2@24.1,5.4 ; v1(22.9,23.5) 23.075,23.325 23.7,23.325 C332.1@23.7,23.3 ; v1(22.9,28.45) 23,28.55 C330.1@23,29 ; J6.16@23.718,90.007 24.611,90.9 C273.1@25.4,90.9 ; FB7.1@25.55,71.9 25.6,71.85 v1(25.6,71.1) ; v1(26.2,11.8) 26.5,11.5 R213.2@26.5,11.3 R213.2@26.5,11.2 ; v1(26.7,93.3) 27,93.3 R258.1@27.5,92.8 ; R133.2@27.5,88 v1(27.5,88.7) R134.2@27.5,89.2 ; R240.2@28.3,60.7 28.7,60.7 v1(29.1,61.1) ; v1(30.8,28.8) C380.1@30.8,29.4 ; R57.2@31.8,59.8 31.8,58.7 v1(32,58.5) 32.2,58.7 R159.2@32.7,58.7 ; R76.2@32.1,38.5 v1(32.8,37.8) ; v1(32.3,61.7) 32.4,61.7 32.8,61.3 R15.2@32.8,61 ; R263.2@32.9,32.5 33.1,32.7 v1(33.7,32.7) ; v1(33.3,10.5) 33.8,11 R201.2@33.8,11.1 ; R116.2@34.3,36.6 34.3,37.6 v1(34.4,37.7) ; v1(37.6,33.4) 37.8,33.2 R132.2@38.2,33.2 ; U33.5@38.25,79.95 38.25,80.95 C414.1@38.1,81.1 38.6,81.1 v1(38.8,80.9) ; R21.2@39.6,73.8 40,73.8 v1(40.3,73.5) ; R118.2@39.6,75.1 39.6,75.2 v1(40.1,75.7) 40.1,75.9 R356.2@39.6,76.4 ; v1(40.6,7.95) 41,8.35 C296.1@41,8.4 ; v1(49.55,92.6) R370.2@50.3,92.6 ; Q8.2@51.75,91.7 v1(52.5,91.7) ; v1(53.5,93.05) 53.7,93.25 R375.2@53.7,93.7 ; Q8.5@53.65,91.7 v1(54.4,91.7) ; v1(54.3,90.5) 54.9,89.9 R376.2@54.9,89.8 ; Q11.2@56.65,91.7 v1(57.4,91.7) ; Q11.5@58.55,91.7 v1(59.3,91.7) ; v1(58.6,93.05) 58.8,93.25 R371.2@58.8,93.7 ; FB33.1@62.4,20.65 62.425,20.675 62.425,21.225 v1@63,21.8 ; C405.1@62.9,23.9 62.9,23.4 v1(63,23.3) ; R226.2@66.7,11.4 v1(67.2,11.9)
  other v1: 31.2,6.7 33.7,9.2 53.9,13.7 54.8,13.7 63,21.9 19.3,24.7 19.9,25.3 18.9,25.4 37.1,29.7 61.2,43.2 62.3,43.2 28,53.7 29.6,53.7 7.6,57.1 13.9,57.7 8.3,57.9 10,80.6 11.4,80.6 53.8,87.6 53.8,88.4
+3V3_COMP: C387.1 C388.1 FB33.2 R243.1 U22.14 | length 5.4
  L1 w0.3: C388.1@59.4,14.6 59.5,14.6 60,15.1 60.5,15.1 60.7,15.3 U22.14@60.7,15.625 ; C388.1@59.45,14.55 59.4,14.5 59.4,14.1 v1(59.6,13.9)
  L1 w0.4: R243.1@64.5,13.3 65,13.3 v1(65.1,13.4)
  L10 w0.4: FB33.2@62.4,19.15 63.25,19.15 v1(64.1,18.3)
+3V3_COMP_IO: C389.1 R110.1 R243.2 R315.2 U22.1 | length 4.6
  L1 w0.3: U22.1@62.275,15.9 62.475,15.7 62.475,14.525 C389.1@62.5,14.5
  L1 w0.4: R110.1@61.2,21.7 61.6,21.7 v1(61.9,21.4) 62,21.3 R315.2@62.5,21.3 ; C389.1@62.5,14.5 62.6,14.5 v1(63.1,14) 63.5,13.6 R243.2@63.5,13.3
+3V3_CSI1: C225.1 C226.1 FB16.2 J7.1 J7.2
+3V3_ETH_AVDDH: C190.1 C199.1 C200.1 C201.1 C202.1 FB7.2 U7.1 U7.12 U7.47 | length 5.7
  L1 w0.25: U7.12@12.85,70.54 v1(12.85,71.2) ; U7.1@18.35,70.54 v1(18.35,71.2) ; U7.47@19.04,69.35 19.6,69.35 v1(19.7,69.25)
  L10 w0.4: C190.1@12.3,71 12.65,71 v1(12.85,71.2) 13.05,71 C200.1@13.4,71 ; C202.1@17.7,70.5 17.7,70.55 v1(18.35,71.2) ; C201.1@19.1,68.3 19.1,68.6 19.7,69.2 v1(19.7,69.25) ; FB7.2@23.95,72 FB7.2@24.05,71.9 FB7.2@24.05,71.75
  other v1: 20.1,71.1
+3V3_GYRO: C400.1 C401.1 FB36.2 R320.1 U28.15 | length 0.8
  L1 w0.3: v1(40.2,29.4) U28.15@40.2,30.225
+3V3_GYRO_IO: C402.1 R312.1 R317.1 R320.2 R383.1 U28.18 | length 5.8
  L1 w0.3: U28.18@41.7,30.225 v1(41.7,31.05)
  L1 w0.4: v1(42,35.8) 42.5,36.3 R312.1@42.7,36.3 ; R317.1@42.7,28.7 43,28.7 v1(43.4,29.1)
  L10 w0.4: R320.2@41.2,28.8 41.6,29.2 C402.1@41.6,30.4 41.6,30.95 v1(41.7,31.05) ; R383.1@41.3,33.1 41.3,32.6 v1(41.5,32.4)
+3V3_HDMI: C214.1 R46.1 U12.2 | length 5.9
  L1 w0.28: C214.1@29.2,79.5 C214.1@29.3,79.5 ; U12.2@31,76.05 31,77.4
  L1 w0.4: R46.1@29.2,80.6 29.3,80.5 C214.1@29.3,79.6 30.1,79.6 31,78.7 31,77.4
+3V3_HDR: C429.1 C430.1 C431.1 C432.2 D38.2 FB39.2 FB40.2 L13.2 R399.2 TP40.1 | length 2
  L10 w0.4: C432.2@14,93.8 R399.2@15.1,93.8 15.4,93.8 v1(15.8,93.4)
  other v1: 62.3,46.7 62.3,47.5 11.2,56.1 12,56.1 18.2,88.5 19.2,88.5 20.2,88.5 21.2,88.5 60.7,89.1 61.5,89.1
+3V3_HDR_J1: C298.2 C419.1 FB40.1 FB42.1 J1.7
+3V3_HDR_J2: C299.1 C300.1 C301.1 FB39.1 FB41.1 J2.1 J2.17 | length 2.5
  L10 w0.4: J2.1@65.5,64.1 65.5,65.2 66,65.7 C301.1@66,66.4
  other v1: 63.9,44.8 63.9,45.6
+3V3_IR: C325.1 C394.1 R226.1 U23.3 | length 4.1
  L10 w0.4: R226.1@65.7,11.4 C394.1@65.7,12.5 C325.1@66.7,12.5 67.76,12.5 U23.3@68.4,13.14
+3V3_LDO: C337.1 FB29.1 TP36.1 U9.39 | length 10.2
  L1 w0.3: v1(29.1,23) 29.35,22.75 U9.39@29.35,22.25
  L10 w0.4: FB29.1@25.9,16.4 27.1,16.4 28.1,17.4 28.1,20.2 27.5,20.8 27.5,21.7 C337.1@28.1,22.3 28.4,22.3 v1(29.1,23)
+3V3_MCU: C219.1 C220.1 C221.1 C222.1 C385.1 D24.2 FB29.2 FB30.2 Q14.2 R270.2 R380.2 R386.2 U6.6 U6.29 U21.5 | length 15.5
  L1 w0.4: C221.1@15.9,24 C222.1@16.9,24 16.9,24.25 17.75,25.1 v1(17.75,25.35) ; v1(18,1.9) 18,1.6 D24.2@18.5,1.1 ; U21.5@19.844,21.25 U21.5@19.85,21.25 20.956,21.25 22.206,22.5 22.6,22.5 v1(22.9,22.8) ; R270.2@20.2,18.8 20.2,18.1 21.1,17.2 v1(21.4,17.2)
  L10 w0.3: v1(17.75,25.35) 17.978,25.35 18.925,24.403 U6.29@18.925,23.85 ; U6.6@21.95,19.525 22.457,19.525 22.757,19.225 v1(22.8,19.225)
  L10 w0.4: R380.2@7.7,23.3 v1(7.7,24) ; Q14.2@12.9,17.15 12.95,17.2 v1(14.3,17.2) ; v1(14.8,15) R386.2@15.4,15
  other v1: 23.6,17
+3V3_MPCIE: C257.1 C258.1 C263.1 C264.1 C265.1 C266.1 C267.1 C268.1 FB9.2 J15.2 J15.24 J15.39 J15.41 J15.52 | length 10.6
  L10 w0.4: J15.52@35.2,23.6 35.2,24.592 36.308,25.7 ; C265.1@36.4,25.7 v1(37.4,25.7) ; C266.1@39.6,13.375 v1(39.6,14) J15.41@39.6,15.4 ; J15.39@40.4,15.4 v1(40.4,14) 40.6,13.8 C263.1@40.6,13.375 ; v1@46.4,22.3 J15.24@46.4,23.6 ; J15.2@58.4,23.6 58.4,22.8 v1(59,22.2)
  other v1: 46.4,22.2
+3V3_USB_HUB: C243.1 C245.2 C250.1 C251.2 C255.1 C256.1 C269.1 C270.1 C271.2 FB19.2 R169.2 R217.2 R283.1 R284.1 R285.2 R286.2 U13.5 U13.10 U13.15 U13.23 U13.29 U13.36 | length 18.1
  L1 w0.25: U13.29@64.7,75.9 v1(64.7,77.1)
  L1 w0.28: v1(58,73.3) 58.2,73.1 U13.5@60.4,73.1 ; v1(61.2,69.5) U13.10@61.2,70.3 ; U13.36@61.2,75.9 v1(61.2,76.7) ; v1(63.7,69.4) U13.15@63.7,70.3 ; U13.23@66,73.1 v1(66.8,73.1)
  L1 w0.4: FB19.2@60.4,68.05 61.25,68.05 v1(61.5,68.3) ; R169.2@64.8,81.3 64.4,81.3 v1(64.1,81.6) 64.8,82.3 R217.2@64.8,82.4 ; R283.1@67.2,69.3 v1(67.2,70) 67.3,70.1 R284.1@67.3,70.6
  L10 w0.4: v1(58,73.3) 58.025,73.325 58.025,73.725 58.2,73.9 C255.1@58.2,74.6 ; v1(61.5,68.3) 62.1,67.7 R285.2@62.2,67.7 ; v1(64.7,77.1) 64.7,77.3 C269.1@65.2,77.8 ; R286.2@66.8,69.4 66.8,69.6 v1(67.2,70) ; v1(66.8,73.1) 66.8,73.044 67.5,72.344 C251.2@67.5,72 67.475,71.975 67.475,70.825 C250.1@67.5,70.8
  other v1: 59.8,77.55
+5V: C73.1 C75.1 C213.1 C237.1 C366.1 C404.1 C434.1 D18.1 FB17.1 FB32.2 FB35.2 FB38.1 FB44.1 R215.1 TP16.1 U1.D10 U1.E9 U9.44 U12.1 | length 9.1
  L1 w0.3: U9.44@31.55,23.45 32.6,23.45 v1(32.8,23.25)
  L1 w0.4: U1.D10@22.8,46.1 v1(23.2,45.7) U1.E9@23.6,45.3 ; v1(28.4,76.4) C213.1@29.3,76.4 U12.1@30.4,76.4 ; v1(65.5,82.3) 65.6,82.4 C237.1@66,82.4 ; R215.1@66,81.3 66.1,81.4 66.1,82.3 C237.1@66,82.4 ; C237.1@66.1,82.4 C237.1@66,82.4
  L10 w0.3: C73.1@23.735,45.4 23.5,45.4 v1(23.2,45.7) 23.5,46 C75.1@23.735,46
  L10 w0.4: FB44.1@7.7,49.4 8,49.4 8.4,49.8 v1(8.4,50.4)
  other v1: 33,18 33.05,18.85 35.8,29.6 35.8,30.4 64.3,66.9 7.9,67.4 64.3,67.7 7.3,67.9 38.7,79.1 41.7,80.6 40,82.4
+5V_FTDI: C421.1 C422.1 D30.1 D38.1 J3.3 R372.2 R377.2 | length 11.6
  L3 w0.5: v1(55.1,90.5) 59.6,86 v1(60,86) 60,88.7 v1(59.6,89.1)
  L10 w0.4: v1(55.1,90.5) R372.2@55.1,91.1 ; v1(59.6,89.1) 60.2,89.7 R377.2@60.2,89.8
+5V_HDMI_CON: C216.1 J5.18 R187.2 R188.2 U12.38 | length 5.1
  L1 w0.28: v1(30.5,81) U12.38@30.5,82.05
  L1 w0.3: J5.18@40.5,85.44 40.5,86.8 v1(40.8,87.1)
  L10 w0.4: R188.2@36.1,86.4 36.1,87 v1(36.2,87.1) ; R187.2@40.8,86.2 v1(40.8,87.1) 40.9,87.2 C216.1@40.9,87.7
+5V_HDR_J1: C238.1 C420.1 D23.1 FB34.1 FB35.1 J1.1 | length 1.2
  L1 w0.4: v1(9.5,65.7) 10.1,66.3 D23.1@10.1,66.7
+5V_HDR_J2: C302.1 C303.1 C304.1 FB31.1 FB32.1 J2.2 J2.4 | length 0.8
  L10 w0.4: C303.1@63.3,65.5 63.3,65 v1(63.5,64.8)
  other v1: 66.9,66.8 67.7,66.8
+5V_MPCIE: C227.1 C228.1 FB17.2 FB37.2 J15.49 J15.51
  other v1: 36.4,14 34.7,14.4
+5V_USB_BOT: C233.1 C235.1 D17.1 FB23.2 FB38.2 J4.1 U17.8 | length 1.4
  L10 w0.4: C235.1@53.2,87.6 v1(53.2,87) 53.2,86.3 D17.1@53.3,86.2
  other v1: 42.4,82.2 42.4,83 48.5,88.7 48.5,89.5
+5V_USB_OTG: C231.1 C232.1 D16.1 FB2.2 J11.1 Q2.3 TP4.1 | length 2.1
  L1 w0.35: C231.1@23.45,6.9 23.6,6.75 J11.1@23.6,4.875
  other v1: 22.6,7 23.3,7.8
+5V_USB_OTG_Q: C230.2 Q1.2 Q2.2 R214.2 U16.5 | length 2.7
  L10 w0.4: R214.2@8,4.1 v1(8.6,4.1) ; v1(10.2,4.2) 10.5,3.9 C230.2@10.5,3.3 10.5,2.4 U16.5@10.65,2.25
+5V_USB_TOP: C234.1 C236.1 D20.1 FB24.1 J4.5 U17.5 | length 2.1
  L10 w0.4: D20.1@55.3,75.8 56.3,75.8 v1(56.5,76) 56.7,75.8 C236.1@57.2,75.8
  other v1: 46.105,82.195 46.105,82.995 48.5,87.1 48.5,87.9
